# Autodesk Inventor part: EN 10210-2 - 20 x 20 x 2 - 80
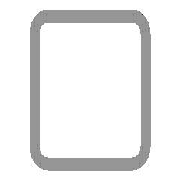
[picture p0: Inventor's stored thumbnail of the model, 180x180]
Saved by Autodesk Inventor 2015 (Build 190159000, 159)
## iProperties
Created: 2014-02
Part Number: EN 10210-2 - 20 x 20 x 2 - 80
Material: Steel, Mild
Description: Tube
Document SubType Name: Modeling
Standard: DIN
Designer: TREINA6
Standard Revision: 1997
Standards Organization: DIN
Language: en-US
Size Designation: 20 x 20 x 2
Categories: <MemberInstance><Categories><Category DisplayName="Structural Shapes" InternalName="089c4875-fa83-4c05-b084-43b9cc11f5ed" Mnemonic="GRDR"><CategoryParameter Dis
Stock Number: 20 x 20 x 2
Density: 7.85 g/cm^3
Appearance: Semi-Polished
IsCustomPart: 1
G_L: 80,000 mm
G_W: 20,000 mm
G_H: 20,000 mm
+79CD6D9C-7958-4B1C-9A20-5A7EB37DBC72+CUTDETAIL1: Cut
_CCFamilyMember: 1
_CCFamilyDisplayName: DIN EN 10210-2 (Square) - Tube
_FrameMemberDoc: Frame Member File
_Version: 15.0.0
_GetPNFromCC: 1
Author: TREINA6
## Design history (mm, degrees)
node "Start plane"
node "End plane"
sketch "Sketch"
  geometry: L1 (-10, -7)-(-10, 7); L2 (-7, 10)-(7, 10); L3 (10, 7)-(10, -7); L4 (7, -10)-(-7, -10); L5 (-7, 8)-(7, 8); L6 (8, 7)-(8, -7); L7 (7, -8)-(-7, -8); L8 (-8, -7)-(-8, 7); L9 (0, 14.87)-(0, -14.87) reference; L10 (-14.87, 0)-(14.87, 0) reference; A1 r 3 centre (-7, -7) between (-10, -7) and (-7, -10); A2 r 3 centre (-7, 7) between (-7, 10) and (-10, 7); A3 r 3 centre (7, 7) between (10, 7) and (7, 10); A4 r 3 centre (7, -7) between (7, -10) and (10, -7); A5 r 1 centre (-7, 7) between (-7, 8) and (-8, 7); A6 r 1 centre (7, 7) between (8, 7) and (7, 8); A7 r 1 centre (7, -7) between (7, -8) and (8, -7); A8 r 1 centre (-7, -7) between (-8, -7) and (-7, -8)
  constraints: 16 end point, 16 point on circle, 8 centre point, 8 tangent, 4 parallel, 3 equal radius, 2 perpendicular, 7 other
  dimensions: "d7" = 3 radius of A1 (= G_IR); "d10" = 20 distance between parallel lines of L2 L4 (= G_H); "d11" = 20 distance between parallel lines of L1 L3 (= G_W); "d12" = 2 distance between parallel lines of L3 L6 (= G_T); "d15" = 10 distance between parallel lines of L2 L10 (= 0.5 x d10); "d16" = 10 distance between parallel lines of L9 L3 (= 0.5 x d11)
extrude "Body" new body sketch "Sketch" stored distance "d3" = 80 (= G_L); taper "d4" = 0 deg
node "Driven Length"
  sketch "Sketch3"
    geometry: L1 (0, 0)-(10, 0) reference
    constraints: 2 end point, 1 horizontal
  workplane "Work Plane3"
  sketch "Sketch4"
    geometry: L1 (-2, 0)-(12, 0) reference; L2 (-2, 80)-(12, 80) reference
    dimensions: "d18" = 80 distance between parallel lines of L1 L2 (derived)
workplane "Work Plane4"
split "Split1"
body "Solid1"
other parameters: "G_W" = 20 [user parameter; used in 1 equation term], "G_H" = 20 [user parameter; used in 1 equation term], "G_T" = 2 [user parameter; used in 1 equation term], "G_IR" = 3 [user parameter; used in 1 equation term], "G_L" = 80 (= d18) [user parameter; used in 1 equation term], "G_OFFSET_START" = 0 [user parameter; used in 1 equation term], "d13" = 0 (computed from G_OFFSET_START), "d17" = 90 deg
